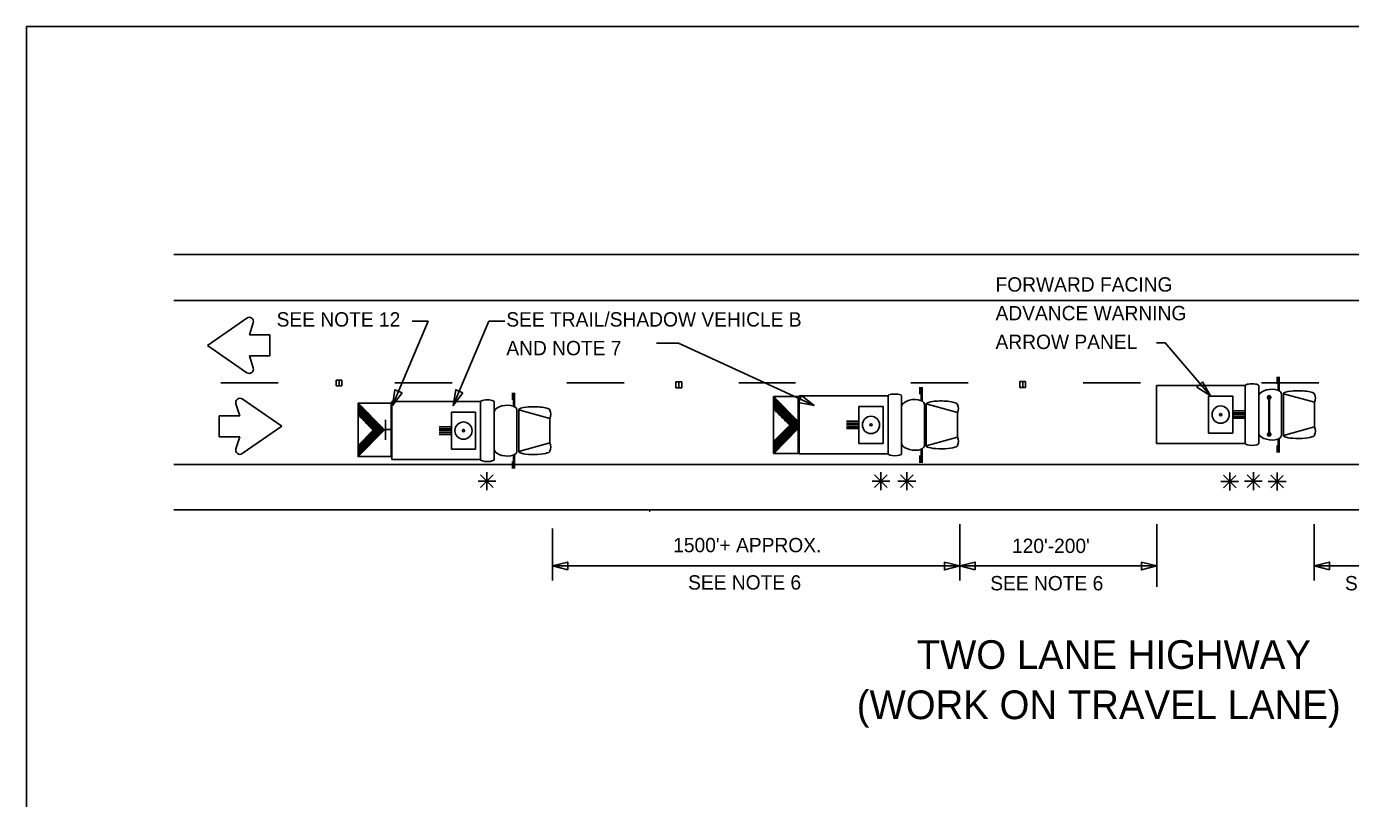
# Model space of a CAD drawing. Extents: x 1416408 to 1429341, y 372694 to 383211.
# Drawn here: x 1426235 to 1427162, y 373939 to 374480 of the extents above; entities that cross this region are included whole.
import ezdxf

# ---------------------------------------------------------------- set-up
doc = ezdxf.new("R2010")
doc.units = 0
for name, color, linetype in [('Default', 7, 'Continuous'), ('DSN_DRFT_Junk-No-Plot', 7, 'Continuous'), ('Level 1', 7, 'Continuous'), ('Working Level 1', 7, 'Continuous')]:
    doc.layers.add(name, color=color, linetype=linetype)

msp = doc.modelspace()

# ---------------------------------------------------------------- linework, layer by layer
at = {"layer": 'Default'}
for points in [[(1426234.86, 374479.9), (1426234.86, 372693.86), (1428995.11, 372693.86), (1428995.11, 374479.9)], [(1426234.86, 374479.9), (1426234.86, 372693.86), (1428995.11, 372693.86), (1428995.11, 374479.9)], [(1426234.86, 374479.9), (1428995.11, 374479.9), (1428995.11, 372693.86), (1426234.86, 372693.86)], [(1426234.86, 374479.9), (1426234.86, 372693.86), (1428995.11, 372693.86), (1428995.11, 374479.9)]]:
    msp.add_lwpolyline(points, close=True, dxfattribs=at)
at = {"layer": 'DSN_DRFT_Junk-No-Plot'}
msp.add_lwpolyline([(1426234.86, 374479.9), (1428995.11, 374479.9), (1428995.11, 372693.86), (1426234.86, 372693.86)], close=True, dxfattribs=at)
at = {"layer": 'Level 1'}
for points in [[(1426491.16, 374214.47), (1426516.08, 374273.51), (1426505, 374273.51)], [(1426533.76, 374214.47), (1426558.68, 374273.51), (1426569.76, 374273.51)], [(1426786.41, 374214.47), (1426691.58, 374258.11), (1426676.12, 374258.11)]]:
    msp.add_lwpolyline(points, dxfattribs=at)
at = {"layer": 'Working Level 1'}
for p, q in [((1426337.99, 374320.17), (1427662.49, 374320.17)), ((1426337.99, 374288.14), (1427662.49, 374288.14)), ((1426361.62, 374256.61), (1426389.23, 374275.76)), ((1426390.97, 374263.92), (1426393.67, 374272.42)), ((1426361.62, 374256.61), (1426389.23, 374237.47)), ((1426405.34, 374263.92), (1426390.97, 374263.92)), ((1426405.34, 374263.92), (1426405.34, 374249.3)), ((1426405.34, 374249.3), (1426390.97, 374249.3)), ((1426390.97, 374249.3), (1426393.67, 374240.81)), ((1426451.75, 374232.23), (1426451.74, 374228.17)), ((1426455.77, 374232.23), (1426451.75, 374232.23)), ((1426453.77, 374232.23), (1426453.76, 374228.17)), ((1426455.77, 374228.17), (1426455.77, 374232.23)), ((1426689.71, 374230.99), (1426689.7, 374226.92)), ((1426693.72, 374230.99), (1426689.71, 374230.99)), ((1426691.72, 374230.99), (1426691.71, 374226.92)), ((1426693.72, 374226.92), (1426693.72, 374230.99)), ((1426930.58, 374231.22), (1426930.57, 374227.15)), ((1426934.59, 374231.22), (1426930.58, 374231.22)), ((1426932.59, 374231.22), (1426932.58, 374227.15)), ((1426934.59, 374227.15), (1426934.59, 374231.22)), ((1427026.17, 374228.42), (1427088.35, 374228.42)), ((1427026.17, 374187.8), (1427026.17, 374228.42)), ((1427026.17, 374228.42), (1427026.17, 374187.81)), ((1427088.35, 374208.11), (1427088.35, 374228.42)), ((1427097.88, 374208.11), (1427097.88, 374228.42)), ((1427110.72, 374229.64), (1427110.72, 374234.6)), ((1427111.5, 374224.85), (1427111.5, 374234.6)), ((1427112.16, 374224.85), (1427112.16, 374234.6)), ((1426413.62, 374199.92), (1426386.01, 374219.08)), ((1426451.74, 374228.17), (1426455.77, 374228.17)), ((1426575.23, 374218.4), (1426575.23, 374223.38)), ((1426576.01, 374213.62), (1426576.01, 374223.38)), ((1426576.68, 374213.62), (1426576.68, 374223.38)), ((1426689.7, 374226.92), (1426693.72, 374226.92)), ((1426758.05, 374220.74), (1426775.21, 374203.41)), ((1426776.04, 374221.22), (1426838.22, 374221.22)), ((1426776.04, 374180.61), (1426776.04, 374221.22)), ((1426838.22, 374200.92), (1426838.22, 374221.22)), ((1426847.75, 374200.92), (1426847.75, 374221.22)), ((1426860.6, 374222.44), (1426860.6, 374227.41)), ((1426861.37, 374217.66), (1426861.37, 374227.41)), ((1426862.03, 374217.66), (1426862.03, 374227.41)), ((1426930.57, 374227.15), (1426934.59, 374227.15)), ((1427062.7, 374221.12), (1427079.69, 374221.12)), ((1427062.7, 374221.12), (1427062.7, 374195.12)), ((1427079.69, 374195.12), (1427079.69, 374221.12)), ((1427103.95, 374220.46), (1427103.95, 374220.46)), ((1427104.98, 374219.88), (1427104.98, 374194.67)), ((1427105.04, 374219.88), (1427105.04, 374194.67)), ((1427105.12, 374219.88), (1427105.12, 374194.67)), ((1427105.25, 374219.88), (1427105.25, 374194.67)), ((1427105.41, 374221.31), (1427105.41, 374221.31)), ((1427105.44, 374219.88), (1427105.44, 374194.67)), ((1427113.84, 374208.11), (1427113.84, 374222.74)), ((1427115.16, 374222.74), (1427136.91, 374216.73)), ((1427115.16, 374208.11), (1427115.16, 374222.74)), ((1426384.27, 374207.23), (1426381.57, 374215.73)), ((1426467.06, 374216.12), (1426485.59, 374197.42)), ((1426490.69, 374217.2), (1426490.69, 374176.59)), ((1426490.69, 374217.19), (1426552.87, 374217.19)), ((1426490.69, 374176.58), (1426490.69, 374217.19)), ((1426549.44, 374209.88), (1426532.45, 374209.88)), ((1426532.45, 374209.88), (1426532.45, 374183.89)), ((1426549.44, 374183.89), (1426549.44, 374209.88)), ((1426552.87, 374196.89), (1426552.87, 374217.19)), ((1426562.39, 374196.89), (1426562.39, 374217.19)), ((1426578.35, 374196.89), (1426578.35, 374211.51)), ((1426579.67, 374211.51), (1426601.42, 374205.5)), ((1426579.67, 374196.89), (1426579.67, 374211.51)), ((1426758.05, 374212.08), (1426769.36, 374200.69)), ((1426834.8, 374213.91), (1426817.8, 374213.91)), ((1426817.8, 374213.91), (1426817.8, 374187.92)), ((1426834.8, 374187.92), (1426834.8, 374213.91)), ((1426863.71, 374200.92), (1426863.71, 374215.55)), ((1426865.03, 374215.55), (1426886.78, 374209.53)), ((1426865.03, 374200.92), (1426865.03, 374215.55)), ((1427079.69, 374210.72), (1427088.35, 374210.72)), ((1427136.91, 374208.11), (1427136.91, 374216.73)), ((1426369.9, 374192.61), (1426369.9, 374207.23)), ((1426369.9, 374207.23), (1426384.27, 374207.23)), ((1426467.06, 374208), (1426477.68, 374197.3)), ((1426486.21, 374190.37), (1426486.21, 374204.46)), ((1426601.42, 374196.89), (1426601.42, 374205.5)), ((1426758.05, 374189.27), (1426769.36, 374200.69)), ((1426817.8, 374203.52), (1426809.15, 374203.52)), ((1426817.8, 374202.22), (1426809.15, 374202.22)), ((1426817.8, 374200.92), (1426809.15, 374200.92)), ((1426838.22, 374200.92), (1426838.22, 374180.62)), ((1426847.75, 374200.92), (1426847.75, 374180.62)), ((1426863.71, 374200.92), (1426863.71, 374186.29)), ((1426865.03, 374200.92), (1426865.03, 374186.29)), ((1426886.78, 374200.92), (1426886.78, 374209.53)), ((1426886.78, 374200.92), (1426886.78, 374192.3)), ((1427079.69, 374209.41), (1427088.35, 374209.41)), ((1427079.69, 374208.11), (1427088.35, 374208.11)), ((1427079.69, 374206.82), (1427088.35, 374206.82)), ((1427079.69, 374205.52), (1427088.35, 374205.52)), ((1427088.35, 374208.11), (1427088.35, 374187.81)), ((1427097.88, 374208.11), (1427097.88, 374187.81)), ((1427113.84, 374208.11), (1427113.84, 374193.49)), ((1427115.16, 374208.11), (1427115.16, 374193.49)), ((1427136.91, 374208.11), (1427136.91, 374199.5)), ((1426369.9, 374192.61), (1426384.27, 374192.61)), ((1426384.27, 374192.61), (1426381.57, 374184.13)), ((1426413.62, 374199.92), (1426386.01, 374180.78)), ((1426467.06, 374186.6), (1426477.68, 374197.3)), ((1426467.17, 374178.78), (1426485.59, 374197.42)), ((1426490.08, 374197.74), (1426486.09, 374197.74)), ((1426532.45, 374199.48), (1426523.79, 374199.48)), ((1426532.45, 374198.19), (1426523.79, 374198.19)), ((1426532.45, 374196.89), (1426523.79, 374196.89)), ((1426532.45, 374195.58), (1426523.79, 374195.58)), ((1426532.45, 374194.28), (1426523.79, 374194.28)), ((1426552.87, 374196.89), (1426552.87, 374176.59)), ((1426562.39, 374196.89), (1426562.39, 374176.59)), ((1426578.35, 374196.89), (1426578.35, 374182.26)), ((1426579.67, 374196.89), (1426579.67, 374182.26)), ((1426601.42, 374196.89), (1426601.42, 374188.26)), ((1426758.15, 374180.93), (1426775.12, 374198.1)), ((1426817.8, 374199.61), (1426809.15, 374199.61)), ((1426817.8, 374198.32), (1426809.15, 374198.32)), ((1426865.03, 374186.29), (1426886.78, 374192.3)), ((1427062.7, 374195.12), (1427079.69, 374195.12)), ((1427104.02, 374194.45), (1427104.02, 374194.45)), ((1427105.47, 374195.3), (1427105.47, 374195.3)), ((1427111.5, 374191.38), (1427111.5, 374181.62)), ((1427112.16, 374191.38), (1427112.16, 374181.62)), ((1427115.16, 374193.49), (1427136.91, 374199.5)), ((1426549.44, 374183.89), (1426532.45, 374183.89)), ((1426579.67, 374182.26), (1426601.42, 374188.26)), ((1426834.8, 374187.92), (1426817.8, 374187.92)), ((1426861.37, 374184.18), (1426861.37, 374174.42)), ((1426862.03, 374184.18), (1426862.03, 374174.42)), ((1427026.17, 374187.81), (1427088.35, 374187.81)), ((1427110.72, 374186.6), (1427110.72, 374181.62)), ((1426337.99, 374173.12), (1427662.49, 374173.12)), ((1426490.69, 374176.59), (1426552.87, 374176.59)), ((1426575.23, 374175.36), (1426575.23, 374170.39)), ((1426576.01, 374180.14), (1426576.01, 374170.39)), ((1426576.68, 374180.14), (1426576.68, 374170.39)), ((1426776.04, 374180.62), (1426838.22, 374180.62)), ((1426860.6, 374179.4), (1426860.6, 374174.42)), ((1426557.35, 374161.61), (1426552.94, 374166.06)), ((1426557.24, 374161.53), (1426561.65, 374165.98)), ((1426557.35, 374161.61), (1426557.35, 374167.91)), ((1426833.25, 374161.61), (1426828.85, 374166.06)), ((1426833.15, 374161.53), (1426837.56, 374165.98)), ((1426833.25, 374161.61), (1426833.25, 374167.91)), ((1426851.44, 374161.61), (1426847.03, 374166.06)), ((1426851.33, 374161.53), (1426855.74, 374165.98)), ((1426851.44, 374161.61), (1426851.44, 374167.91)), ((1427077.54, 374161.21), (1427073.13, 374165.66)), ((1427077.43, 374161.13), (1427081.84, 374165.58)), ((1427077.54, 374161.21), (1427077.54, 374167.51)), ((1427094.14, 374161.61), (1427089.73, 374166.06)), ((1427094.03, 374161.53), (1427098.44, 374165.98)), ((1427094.14, 374161.61), (1427094.14, 374167.91)), ((1427110.74, 374161.21), (1427106.33, 374165.66)), ((1427110.63, 374161.13), (1427115.05, 374165.58)), ((1427110.74, 374161.21), (1427110.74, 374167.51)), ((1426557.35, 374161.61), (1426551.11, 374161.61)), ((1426557.35, 374161.61), (1426552.94, 374157.15)), ((1426557.35, 374161.61), (1426561.75, 374157.15)), ((1426557.35, 374161.61), (1426557.35, 374155.31)), ((1426557.35, 374161.61), (1426563.57, 374161.61)), ((1426833.25, 374161.61), (1426827.02, 374161.61)), ((1426833.25, 374161.61), (1426828.85, 374157.15)), ((1426833.25, 374161.61), (1426837.66, 374157.15)), ((1426833.25, 374161.61), (1426833.25, 374155.31)), ((1426833.25, 374161.61), (1426839.48, 374161.61)), ((1426851.44, 374161.61), (1426845.2, 374161.61)), ((1426851.44, 374161.61), (1426847.03, 374157.15)), ((1426851.44, 374161.61), (1426855.84, 374157.15)), ((1426851.44, 374161.61), (1426851.44, 374155.31)), ((1426851.44, 374161.61), (1426857.66, 374161.61)), ((1427077.54, 374161.21), (1427071.3, 374161.21)), ((1427077.54, 374161.21), (1427073.13, 374156.76)), ((1427077.54, 374161.21), (1427081.94, 374156.76)), ((1427077.54, 374161.21), (1427077.54, 374154.91)), ((1427077.54, 374161.21), (1427083.76, 374161.21)), ((1427094.14, 374161.61), (1427087.9, 374161.61)), ((1427094.14, 374161.61), (1427089.73, 374157.15)), ((1427094.14, 374161.61), (1427098.54, 374157.15)), ((1427094.14, 374161.61), (1427094.14, 374155.31)), ((1427094.14, 374161.61), (1427100.36, 374161.61)), ((1427110.74, 374161.21), (1427104.5, 374161.21)), ((1427110.74, 374161.21), (1427106.33, 374156.76)), ((1427110.74, 374161.21), (1427115.14, 374156.76)), ((1427110.74, 374161.21), (1427110.74, 374154.91)), ((1427110.74, 374161.21), (1427116.97, 374161.21)), ((1426337.99, 374141.51), (1427662.49, 374141.51)), ((1426671.66, 374140.5), (1426670.86, 374140.5)), ((1426603.2, 374128.45), (1426603.2, 374091.96)), ((1426888.49, 374131.36), (1426888.49, 374091.96)), ((1427026.44, 374131.36), (1427026.44, 374087.53)), ((1427136.72, 374131.36), (1427136.72, 374091.96)), ((1426603.2, 374102.12), (1426888.49, 374102.12)), ((1426603.2, 374102.12), (1426612.75, 374102.12)), ((1426888.49, 374102.12), (1426886.58, 374102.12)), ((1426888.49, 374102.12), (1426896.02, 374102.12)), ((1426888.49, 374102.12), (1427026.44, 374102.12)), ((1427026.44, 374102.12), (1427018.96, 374102.12)), ((1427136.72, 374102.12), (1427144.24, 374102.12)), ((1427136.87, 374102.12), (1427274.82, 374102.12))]:
    msp.add_line(p, q, dxfattribs=at)
for points in [[(1427064.02, 374221.34), (1427032.4, 374258.48), (1427026.37, 374258.48)], [(1426370.86, 374230.45), (1426411.03, 374230.45)], [(1426492.82, 374230.45), (1426532.99, 374230.45)], [(1426613.31, 374230.45), (1426653.48, 374230.45)], [(1426733.8, 374230.45), (1426773.47, 374230.45)], [(1426854.29, 374230.45), (1426894.46, 374230.45)], [(1426974.79, 374230.45), (1427014.96, 374230.45)], [(1427099.82, 374230.45), (1427139.99, 374230.45)], [(1426758.05, 374219.82), (1426768.47, 374201.57)], [(1426758.92, 374219.87), (1426772.72, 374195.7)], [(1427103.92, 374220.02), (1427104.36, 374219.26)], [(1427103.95, 374220.46), (1427104.75, 374219.04)], [(1427104.05, 374220.76), (1427105.07, 374218.98)], [(1427104.2, 374220.99), (1427105.33, 374219.01)], [(1427104.38, 374221.16), (1427105.57, 374219.08)], [(1427104.58, 374221.3), (1427105.78, 374219.19)], [(1427104.82, 374221.37), (1427105.96, 374219.36)], [(1427105.07, 374221.42), (1427106.13, 374219.57)], [(1427105.37, 374221.38), (1427106.24, 374219.84)], [(1427105.72, 374221.25), (1427106.31, 374220.23)], [(1426467.06, 374215.24), (1426476.84, 374198.14)], [(1426467.06, 374213.77), (1426474.91, 374200.04)], [(1426467.06, 374212.3), (1426472.97, 374201.96)], [(1426467.06, 374210.83), (1426471.03, 374203.89)], [(1426467.89, 374215.3), (1426480.83, 374192.62)], [(1426469.87, 374213.28), (1426481.36, 374193.15)], [(1426471.85, 374211.28), (1426481.9, 374193.7)], [(1426758.05, 374218.26), (1426766.4, 374203.61)], [(1426758.05, 374216.68), (1426764.34, 374205.65)], [(1426758.05, 374215.11), (1426762.28, 374207.7)], [(1426758.05, 374213.54), (1426760.22, 374209.74)], [(1426758.05, 374211.97), (1426758.15, 374211.79)], [(1426761.04, 374217.72), (1426773.29, 374196.26)], [(1426763.16, 374215.59), (1426773.86, 374196.84)], [(1426765.28, 374213.44), (1426774.43, 374197.41)], [(1426767.39, 374211.31), (1426775, 374197.98)], [(1426467.06, 374209.35), (1426469.1, 374205.8)], [(1426467.06, 374207.88), (1426467.17, 374207.72)], [(1426473.85, 374209.27), (1426482.43, 374194.23)], [(1426475.82, 374207.26), (1426482.96, 374194.77)], [(1426477.81, 374205.25), (1426483.52, 374195.28)], [(1426479.8, 374203.25), (1426484.06, 374195.79)], [(1426481.79, 374201.26), (1426484.55, 374196.4)], [(1426769.51, 374209.17), (1426775.14, 374199.31)], [(1426771.63, 374207.03), (1426775.16, 374200.85)], [(1426773.74, 374204.9), (1426775.19, 374202.36)], [(1426472.11, 374191.7), (1426474.96, 374186.72)], [(1426472.64, 374192.24), (1426475.49, 374187.25)], [(1426473.17, 374192.77), (1426476.02, 374187.79)], [(1426473.71, 374193.31), (1426476.57, 374188.31)], [(1426474.24, 374193.85), (1426477.09, 374188.87)], [(1426474.77, 374194.38), (1426477.63, 374189.39)], [(1426475.31, 374194.93), (1426478.17, 374189.93)], [(1426475.84, 374195.46), (1426478.7, 374190.47)], [(1426476.38, 374195.99), (1426479.23, 374191)], [(1426476.9, 374196.54), (1426479.77, 374191.55)], [(1426477.45, 374197.08), (1426480.3, 374192.08)], [(1426483.62, 374199.43), (1426485.05, 374196.92)], [(1426760.02, 374191.26), (1426763.05, 374185.95)], [(1426760.58, 374191.83), (1426763.61, 374186.54)], [(1426761.15, 374192.41), (1426764.18, 374187.1)], [(1426761.72, 374192.97), (1426764.75, 374187.68)], [(1426762.3, 374193.55), (1426765.32, 374188.24)], [(1426762.87, 374194.13), (1426765.89, 374188.81)], [(1426763.43, 374194.71), (1426766.46, 374189.39)], [(1426763.99, 374195.28), (1426767.03, 374189.96)], [(1426764.56, 374195.85), (1426767.6, 374190.54)], [(1426765.14, 374196.42), (1426768.18, 374191.11)], [(1426765.7, 374197), (1426768.74, 374191.69)], [(1426766.27, 374197.57), (1426769.31, 374192.25)], [(1426766.83, 374198.15), (1426769.87, 374192.82)], [(1426767.41, 374198.73), (1426770.44, 374193.4)], [(1426767.98, 374199.3), (1426771.01, 374193.97)], [(1426768.54, 374199.86), (1426771.59, 374194.55)], [(1426769.11, 374200.44), (1426772.16, 374195.12)], [(1427103.99, 374194.01), (1427104.43, 374193.24)], [(1427104.02, 374194.45), (1427104.83, 374193.04)], [(1427104.12, 374194.76), (1427105.13, 374192.98)], [(1427104.27, 374194.99), (1427105.4, 374193)], [(1427104.45, 374195.15), (1427105.64, 374193.08)], [(1427104.65, 374195.29), (1427105.85, 374193.19)], [(1427104.89, 374195.35), (1427106.04, 374193.34)], [(1427105.13, 374195.41), (1427106.19, 374193.56)], [(1427105.44, 374195.38), (1427106.32, 374193.83)], [(1427105.8, 374195.25), (1427106.38, 374194.22)], [(1426467.06, 374185.8), (1426469.62, 374181.34)], [(1426467.06, 374184.33), (1426469.08, 374180.8)], [(1426467.06, 374182.86), (1426468.55, 374180.27)], [(1426467.31, 374186.85), (1426470.15, 374181.89)], [(1426467.85, 374187.39), (1426470.69, 374182.41)], [(1426468.38, 374187.92), (1426471.21, 374182.96)], [(1426468.92, 374188.47), (1426471.76, 374183.48)], [(1426469.44, 374189), (1426472.29, 374184.04)], [(1426469.98, 374189.54), (1426472.82, 374184.56)], [(1426470.51, 374190.07), (1426473.36, 374185.1)], [(1426471.05, 374190.62), (1426473.9, 374185.64)], [(1426471.58, 374191.15), (1426474.43, 374186.17)], [(1426758.05, 374188.43), (1426760.77, 374183.66)], [(1426758.05, 374186.85), (1426760.2, 374183.09)], [(1426758.05, 374185.27), (1426759.63, 374182.52)], [(1426758.05, 374183.71), (1426759.06, 374181.94)], [(1426758.05, 374182.14), (1426758.49, 374181.38)], [(1426758.31, 374189.53), (1426761.33, 374184.24)], [(1426758.88, 374190.11), (1426761.91, 374184.8)], [(1426759.44, 374190.67), (1426762.47, 374185.39)], [(1426467.06, 374181.38), (1426468.02, 374179.73)], [(1426467.06, 374179.91), (1426467.48, 374179.21)]]:
    msp.add_lwpolyline(points, dxfattribs=at)
for points in [[(1427058.42, 374231.03), (1427064.02, 374221.34), (1427054.57, 374227.22)], [(1426497.86, 374223.41), (1426491.16, 374214.47), (1426492.91, 374225.54)], [(1426540.46, 374223.41), (1426533.76, 374214.47), (1426535.51, 374225.54)], [(1426775.25, 374180.93), (1426758.05, 374180.93), (1426758.05, 374220.74), (1426775.25, 374220.74)], [(1426777.72, 374221.45), (1426786.41, 374214.47), (1426775.49, 374216.5)], [(1426467.06, 374216.12), (1426467.06, 374178.77), (1426490.15, 374178.77), (1426490.15, 374216.12)], [(1426613.96, 374099.4), (1426603.2, 374102.12), (1426613.96, 374104.84)], [(1426877.73, 374104.84), (1426888.49, 374102.12), (1426877.73, 374099.4)], [(1426899.26, 374099.4), (1426888.49, 374102.12), (1426899.26, 374104.84)], [(1427015.67, 374104.84), (1427026.44, 374102.12), (1427015.67, 374099.4)], [(1427147.48, 374099.4), (1427136.72, 374102.12), (1427147.48, 374104.84)]]:
    msp.add_lwpolyline(points, close=True, dxfattribs=at)
for centre, major_axis, ratio, start_param, end_param in [((1426390.88, 374273.32), (0, -2.96), 0.989089, 1.259821, 3.74278), ((1426390.88, 374239.91), (0, -2.96), 0.989089, 5.681999, 8.164958), ((1427093.11, 374228.42), (4.76, 0), 0.27289, 6.283185, 9.424778), ((1426384.36, 374216.63), (0, 2.96), 0.989089, 5.681999, 8.164958), ((1426842.99, 374221.22), (4.76, 0), 0.27289, 6.283185, 9.424778), ((1427105.86, 374221.74), (7.98, 1.01), 0.50847, 6.28135, 9.422943), ((1427126.03, 374222.62), (10.87, -0.13), 0.205643, 0.000054, 3.141647), ((1427131.58, 374219.61), (0, 6.1), 0.989089, 4.221603, 5.203174), ((1426557.63, 374217.19), (4.76, 0), 0.27289, 6.283185, 9.424778), ((1426570.37, 374210.51), (7.98, 1.01), 0.50847, 6.28135, 9.422943), ((1426590.55, 374211.38), (10.87, -0.13), 0.205643, 0.000054, 3.141647), ((1426596.1, 374208.38), (0, 6.1), 0.989089, 4.221603, 5.203174), ((1426855.73, 374214.54), (7.98, 1.01), 0.50847, 6.28135, 9.422943), ((1426875.91, 374215.42), (10.87, -0.13), 0.205643, 0.000054, 3.141647), ((1426881.46, 374212.41), (0, 6.1), 0.989089, 4.221603, 5.203174), ((1426881.46, 374189.43), (0, 6.1), 0.989089, 4.221604, 5.203174), ((1427105.86, 374194.49), (7.98, -1.01), 0.50847, 3.143427, 6.28502), ((1427126.03, 374193.62), (10.87, 0.13), 0.205643, 3.141539, 6.283131), ((1427131.58, 374196.62), (0, 6.1), 0.989089, 4.221604, 5.203174), ((1426384.36, 374183.22), (0, 2.96), 0.989089, 1.259821, 3.74278), ((1426570.37, 374183.26), (7.98, -1.01), 0.50847, 3.143427, 6.28502), ((1426590.55, 374182.38), (10.87, 0.13), 0.205643, 3.141539, 6.283131), ((1426596.1, 374185.39), (0, 6.1), 0.989089, 4.221604, 5.203174), ((1426855.73, 374187.29), (7.98, -1.01), 0.50847, 3.143427, 6.28502), ((1426875.91, 374186.42), (10.87, 0.13), 0.205643, 3.141539, 6.283131), ((1427093.11, 374187.81), (4.76, 0), 0.27289, 3.141593, 6.283185), ((1426557.63, 374176.58), (4.76, 0), 0.27289, 3.141593, 6.283185), ((1426842.99, 374180.61), (4.76, 0), 0.27289, 3.141593, 6.283185)]:
    msp.add_ellipse(centre, major_axis=major_axis, ratio=ratio, start_param=start_param, end_param=end_param, dxfattribs=at)
for centre, major_axis in [((1427105.11, 374220.2), (0, -1.22)), ((1427071.19, 374208.12), (0, -6.07)), ((1426540.95, 374196.88), (0, 6.07)), ((1426826.3, 374200.92), (0, 6.07)), ((1426826.3, 374200.92), (0, -0.755)), ((1427071.19, 374208.12), (0, 0.755)), ((1426540.95, 374196.88), (0, -0.755)), ((1427105.18, 374194.2), (0, -1.22))]:
    msp.add_ellipse(centre, major_axis=major_axis, ratio=0.989089, dxfattribs=at)

# ---------------------------------------------------------------- texts
for s, height, p in [('FORWARD FACING', 10.0465, (1426913.53, 374294.24)), ('ADVANCE WARNING ', 10.0465, (1426913.53, 374274.15)), ('SEE NOTE 12 ', 10.0465, (1426410.05, 374269.78)), ('SEE TRAIL/SHADOW VEHICLE B', 10.0465, (1426570.91, 374269.78)), ('AND NOTE 7 ', 10.0465, (1426570.91, 374249.68)), ('ARROW PANEL', 10.0465, (1426913.53, 374254.05)), ("1500'+ APPROX.", 10.0465, (1426687.79, 374111.74)), ("120'-200'", 10.046, (1426925.07, 374111.2)), ('SEE NOTE 6', 10.046, (1426698.24, 374085.59)), ('SEE NOTE 6', 10.046, (1426909.85, 374085.05)), ('SEE NOTE 6', 10.046, (1427158.23, 374085.05)), ('TWO LANE HIGHWAY', 20.0929, (1426858.28, 374030.03)), ('(WORK ON TRAVEL LANE)', 20.0929, (1426816.34, 373994.87))]:
    msp.add_text(s, height=height, dxfattribs=at).set_placement(p)

doc.saveas('drawing.dxf')
